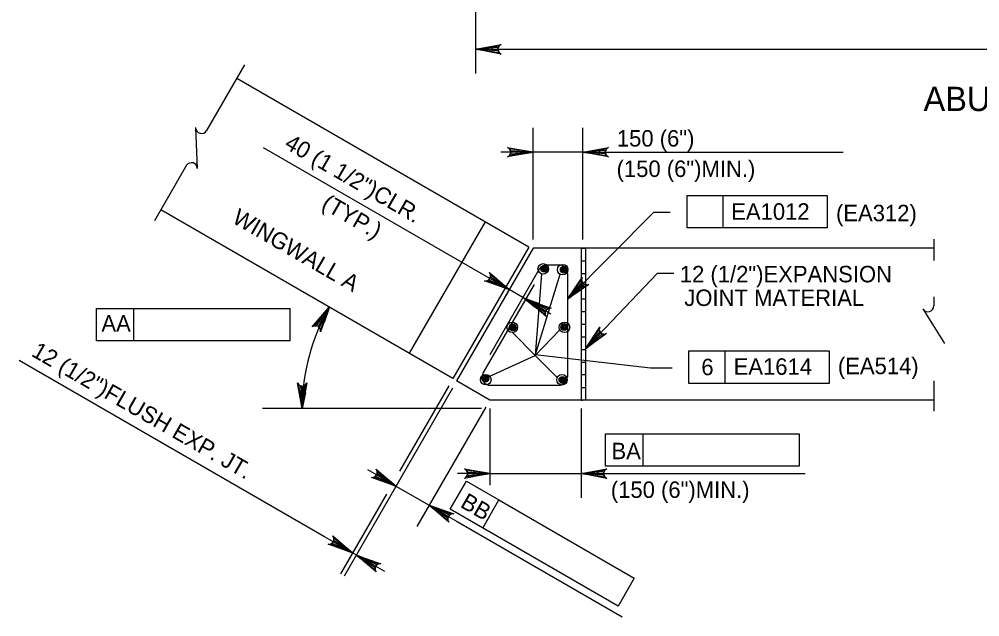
# Model space of a CAD drawing. Extents: x 634540 to 640306, y 296059 to 300275.
# Drawn here: x 638533.4 to 638708.4, y 297521.6 to 297630.5 of the extents above; entities that cross this region are included whole.
import ezdxf

# ---------------------------------------------------------------- set-up
doc = ezdxf.new("R2010")
doc.units = 0
for name, color, linetype in [('10', 7, 'Continuous'), ('3', 7, 'Continuous'), ('4', 7, 'Continuous'), ('5', 7, 'Continuous')]:
    doc.layers.add(name, color=color, linetype=linetype)

msp = doc.modelspace()

# ---------------------------------------------------------------- linework, layer by layer
at = {"layer": '10'}
for p, q in [((638626.27, 297588.96), (638573.04, 297619.69)), ((638612.43, 297564.99), (638559.2, 297595.72)), ((638618.28, 297593.57), (638604.43, 297569.6)), ((638626.27, 297588.96), (638612.43, 297564.99)), ((638627.05, 297588.78), (638613.09, 297564.6)), ((638700.05, 297588.78), (638627.05, 297588.78)), ((638635.82, 297588.77), (638635.82, 297561.09)), ((638636.59, 297588.77), (638636.59, 297561.09)), ((638619.17, 297561.09), (638613.09, 297564.6)), ((638700.05, 297561.09), (638619.17, 297561.09))]:
    msp.add_line(p, q, dxfattribs=at)
at = {"layer": '3'}
for p, q in [((638616.53, 297669.3), (638616.53, 297620.56)), ((638616.53, 297624.99), (638844.8, 297624.99)), ((638627.05, 297590.31), (638627.05, 297610.68)), ((638636.11, 297590.31), (638636.11, 297610.68)), ((638617.57, 297584.16), (638577.89, 297607.06)), ((638627.05, 297606.25), (638621.15, 297606.25)), ((638636.11, 297606.25), (638627.05, 297606.25)), ((638636.11, 297606.25), (638683.51, 297606.25)), ((638655.09, 297598.35), (638680.63, 297598.35)), ((638655.09, 297592.44), (638655.09, 297598.35)), ((638661.68, 297592.44), (638661.68, 297598.35)), ((638680.63, 297598.35), (638680.63, 297592.44)), ((638633.28, 297579.48), (638649.06, 297595.29)), ((638649.06, 297595.29), (638652.01, 297595.29)), ((638680.63, 297592.44), (638655.09, 297592.44)), ((638622.68, 297581.2), (638617.57, 297584.16)), ((638636.59, 297570.41), (638649.72, 297584.22)), ((638649.72, 297584.22), (638652.67, 297584.22)), ((638622.44, 297580.79), (638620.46, 297577.37)), ((638547.46, 297577.77), (638554.31, 297577.77)), ((638547.46, 297571.87), (638547.46, 297577.77)), ((638554.31, 297571.87), (638554.31, 297577.77)), ((638554.31, 297577.77), (638582.76, 297577.77)), ((638582.76, 297571.87), (638582.76, 297577.77)), ((638582.76, 297571.87), (638547.46, 297571.87)), ((638655.43, 297570.03), (638680.97, 297570.03)), ((638655.43, 297564.12), (638655.43, 297570.03)), ((638662.03, 297564.12), (638662.03, 297570.03)), ((638680.97, 297570.03), (638680.97, 297564.12)), ((638589.04, 297536.19), (638533.4, 297568.32)), ((638648.41, 297566.97), (638652.36, 297566.97)), ((638612.32, 297563.27), (638592.61, 297529.02)), ((638611.66, 297563.65), (638602.72, 297548.14)), ((638680.97, 297564.12), (638655.43, 297564.12)), ((638617.63, 297559.55), (638577.73, 297559.55)), ((638618.4, 297559.76), (638605.88, 297538.07)), ((638619.17, 297559.55), (638619.17, 297545.57)), ((638635.82, 297559.55), (638635.82, 297543.27)), ((638640.23, 297549.03), (638640.23, 297554.94)), ((638640.23, 297554.94), (638647.07, 297554.94)), ((638647.07, 297549.03), (638647.07, 297554.94)), ((638647.07, 297554.94), (638675.53, 297554.94)), ((638675.53, 297554.94), (638675.53, 297549.03)), ((638675.53, 297549.03), (638640.23, 297549.03)), ((638599.46, 297546.9), (638596.9, 297548.37)), ((638616.22, 297547.7), (638613.27, 297547.7)), ((638619.17, 297547.7), (638643.53, 297547.7)), ((638638.77, 297547.7), (638641.72, 297547.7)), ((638641.72, 297547.7), (638676.59, 297547.7)), ((638602.02, 297545.42), (638608.1, 297541.91)), ((638611.94, 297541.19), (638614.89, 297546.31)), ((638614.89, 297546.31), (638620.82, 297542.88)), ((638600.3, 297543.93), (638591.94, 297529.41)), ((638617.87, 297537.77), (638620.82, 297542.88)), ((638620.82, 297542.88), (638645.47, 297528.65)), ((638610.65, 297540.43), (638613.21, 297538.96)), ((638642.51, 297523.54), (638611.94, 297541.19)), ((638613.21, 297538.96), (638643.27, 297521.6)), ((638591.6, 297534.72), (638589.04, 297536.19)), ((638594.82, 297532.86), (638594.15, 297533.24)), ((638597.38, 297531.38), (638599.93, 297529.91)), ((638645.47, 297528.65), (638642.51, 297523.54))]:
    msp.add_line(p, q, dxfattribs=at)
for points in [[(638616.53, 297624.99), (638621.2, 297625.87), (638620.84, 297625.62), (638620.65, 297625.31), (638620.6, 297624.99), (638620.65, 297624.68), (638620.84, 297624.37), (638621.2, 297624.12), (638616.53, 297624.99), (638620.84, 297624.37), (638620.65, 297624.68), (638616.53, 297624.99), (638620.6, 297624.99), (638620.65, 297625.31), (638616.53, 297624.99), (638620.84, 297625.62)], [(638627.05, 297606.25), (638622.39, 297605.38), (638622.75, 297605.62), (638622.93, 297605.94), (638622.99, 297606.25), (638622.93, 297606.56), (638622.75, 297606.87), (638622.39, 297607.12), (638627.05, 297606.25), (638622.75, 297606.87), (638622.93, 297606.56), (638627.05, 297606.25), (638622.99, 297606.25), (638622.93, 297605.94), (638627.05, 297606.25), (638622.75, 297605.62)], [(638636.11, 297606.25), (638640.77, 297607.12), (638640.41, 297606.87), (638640.23, 297606.56), (638640.17, 297606.25), (638640.23, 297605.94), (638640.41, 297605.62), (638640.77, 297605.38), (638636.11, 297606.25), (638640.41, 297605.62), (638640.23, 297605.94), (638636.11, 297606.25), (638640.17, 297606.25), (638640.23, 297606.56), (638636.11, 297606.25), (638640.41, 297606.87)], [(638622.68, 297581.2), (638618.2, 297582.78), (638618.64, 297582.82), (638618.96, 297582.99), (638619.16, 297583.24), (638619.27, 297583.53), (638619.27, 297583.9), (638619.08, 297584.29), (638622.68, 297581.2), (638619.27, 297583.9), (638619.27, 297583.53), (638622.68, 297581.2), (638619.16, 297583.24), (638618.96, 297582.99), (638622.68, 297581.2), (638618.64, 297582.82)], [(638633.28, 297579.48), (638635.95, 297583.39), (638635.87, 297582.97), (638635.96, 297582.61), (638636.15, 297582.36), (638636.41, 297582.17), (638636.76, 297582.08), (638637.19, 297582.16), (638633.28, 297579.48), (638636.76, 297582.08), (638636.41, 297582.17), (638633.28, 297579.48), (638636.15, 297582.36), (638635.96, 297582.61), (638633.28, 297579.48), (638635.87, 297582.97)], [(638589.88, 297578), (638588.32, 297573.53), (638588.28, 297573.96), (638588.1, 297574.28), (638587.86, 297574.48), (638587.56, 297574.59), (638587.2, 297574.58), (638586.8, 297574.4), (638589.88, 297578), (638587.2, 297574.58), (638587.56, 297574.59), (638589.88, 297578), (638587.86, 297574.48), (638588.1, 297574.28), (638589.88, 297578), (638588.28, 297573.96)], [(638636.59, 297570.41), (638639.17, 297574.39), (638639.1, 297573.95), (638639.2, 297573.6), (638639.39, 297573.35), (638639.65, 297573.17), (638640, 297573.09), (638640.43, 297573.18), (638636.59, 297570.41), (638640, 297573.09), (638639.65, 297573.17), (638636.59, 297570.41), (638639.39, 297573.35), (638639.2, 297573.6), (638636.59, 297570.41), (638639.1, 297573.95)], [(638584.96, 297559.55), (638584.08, 297564.21), (638584.33, 297563.86), (638584.65, 297563.67), (638584.96, 297563.62), (638585.27, 297563.67), (638585.58, 297563.86), (638585.83, 297564.21), (638584.96, 297559.55), (638585.58, 297563.86), (638585.27, 297563.67), (638584.96, 297559.55), (638584.96, 297563.62), (638584.65, 297563.67), (638584.96, 297559.55), (638584.33, 297563.86)], [(638602.04, 297545.41), (638597.57, 297546.98), (638598, 297547.02), (638598.32, 297547.2), (638598.52, 297547.44), (638598.63, 297547.74), (638598.63, 297548.1), (638598.44, 297548.5), (638602.04, 297545.41), (638598.63, 297548.1), (638598.63, 297547.74), (638602.04, 297545.41), (638598.52, 297547.44), (638598.32, 297547.2), (638602.04, 297545.41), (638598, 297547.02)], [(638619.17, 297547.7), (638614.51, 297546.82), (638614.87, 297547.07), (638615.06, 297547.38), (638615.11, 297547.7), (638615.06, 297548.01), (638614.87, 297548.32), (638614.51, 297548.57), (638619.17, 297547.7), (638614.87, 297548.32), (638615.06, 297548.01), (638619.17, 297547.7), (638615.11, 297547.7), (638615.06, 297547.38), (638619.17, 297547.7), (638614.87, 297547.07)], [(638635.82, 297547.7), (638640.48, 297548.57), (638640.12, 297548.32), (638639.94, 297548.01), (638639.88, 297547.7), (638639.94, 297547.38), (638640.12, 297547.07), (638640.48, 297546.82), (638635.82, 297547.7), (638640.12, 297547.07), (638639.94, 297547.38), (638635.82, 297547.7), (638639.88, 297547.7), (638639.94, 297548.01), (638635.82, 297547.7), (638640.12, 297548.32)], [(638608.1, 297541.91), (638612.57, 297540.34), (638612.13, 297540.3), (638611.82, 297540.12), (638611.62, 297539.88), (638611.51, 297539.58), (638611.51, 297539.22), (638611.7, 297538.82), (638608.1, 297541.91), (638611.51, 297539.22), (638611.51, 297539.58), (638608.1, 297541.91), (638611.62, 297539.88), (638611.82, 297540.12), (638608.1, 297541.91), (638612.13, 297540.3)], [(638594.15, 297533.24), (638589.68, 297534.82), (638590.11, 297534.85), (638590.43, 297535.03), (638590.63, 297535.28), (638590.74, 297535.57), (638590.74, 297535.94), (638590.55, 297536.33), (638594.15, 297533.24), (638590.74, 297535.94), (638590.74, 297535.57), (638594.15, 297533.24), (638590.63, 297535.28), (638590.43, 297535.03), (638594.15, 297533.24), (638590.11, 297534.85)], [(638594.83, 297532.85), (638599.3, 297531.28), (638598.87, 297531.24), (638598.55, 297531.07), (638598.35, 297530.82), (638598.24, 297530.52), (638598.24, 297530.16), (638598.43, 297529.77), (638594.83, 297532.85), (638598.24, 297530.16), (638598.24, 297530.52), (638594.83, 297532.85), (638598.35, 297530.82), (638598.55, 297531.07), (638594.83, 297532.85), (638598.87, 297531.24)]]:
    msp.add_lwpolyline(points, dxfattribs=at)
for points in [[(638619.49, 297625.48), (638619.49, 297624.5), (638616.53, 297624.99)], [(638624.1, 297606.74), (638624.1, 297605.76), (638627.05, 297606.25)], [(638639.06, 297606.74), (638639.06, 297605.76), (638636.11, 297606.25)], [(638620.37, 297583.11), (638619.88, 297582.26), (638622.68, 297581.21)], [(638588.98, 297575.22), (638588.11, 297575.67), (638589.92, 297578.06)], [(638584.58, 297562.53), (638585.57, 297562.49), (638584.96, 297559.55)], [(638599.71, 297547.32), (638599.22, 297546.47), (638602.02, 297545.42)], [(638616.22, 297548.19), (638616.22, 297547.2), (638619.17, 297547.7)], [(638638.77, 297548.19), (638638.77, 297547.2), (638635.82, 297547.7)], [(638610.9, 297540.86), (638610.41, 297540.01), (638608.1, 297541.91)], [(638591.84, 297535.14), (638591.35, 297534.29), (638594.15, 297533.24)], [(638597.62, 297531.81), (638597.13, 297530.96), (638594.82, 297532.86)]]:
    msp.add_lwpolyline(points, close=True, dxfattribs=at)
msp.add_arc((638621.97, 297559.55), 37.01, 150.1038, 180, dxfattribs=at)
at = {"layer": '4'}
for p, q in [((638574.47, 297622.17), (638567.54, 297610.18)), ((638565.55, 297610.71), (638565.83, 297603.29)), ((638563.9, 297603.87), (638558.06, 297593.75)), ((638700.05, 297590.42), (638700.05, 297586.53)), ((638700.05, 297579.9), (638700.05, 297578.23)), ((638698.06, 297577.7), (638702.01, 297571.41)), ((638700.05, 297564.58), (638700.05, 297559.07))]:
    msp.add_line(p, q, dxfattribs=at)
for centre, start, end in [((638566.62, 297610.71), 180, 330), ((638564.77, 297603.25), 2.1328, 144.6714), ((638698.98, 297578.23), 210, 0)]:
    msp.add_arc(centre, 1.07, start, end, dxfattribs=at)
at = {"layer": '5'}
for p, q in [((638635.82, 297588.77), (638636.59, 297588.78)), ((638629.49, 297585.69), (638631.74, 297585.69)), ((638635.82, 297586.47), (638636.59, 297586.47)), ((638628.16, 297584.92), (638619.14, 297569.3)), ((638628.57, 297584.07), (638627.39, 297569.21)), ((638627.39, 297569.21), (638631.95, 297584)), ((638633.28, 297584.16), (638633.28, 297565.31)), ((638635.82, 297584.16), (638636.59, 297584.16)), ((638627.22, 297582.15), (638617.95, 297566.08)), ((638625.18, 297579.76), (638622.68, 297581.21)), ((638635.82, 297581.86), (638636.59, 297581.86)), ((638625.84, 297579.38), (638630.29, 297576.81)), ((638635.82, 297579.55), (638636.59, 297579.55)), ((638635.82, 297577.24), (638636.59, 297577.24)), ((638623.29, 297573.38), (638627.39, 297569.21)), ((638627.39, 297569.21), (638631.91, 297573.87)), ((638635.82, 297574.93), (638636.59, 297574.93)), ((638635.82, 297572.63), (638636.59, 297572.63)), ((638635.82, 297570.32), (638636.59, 297570.32)), ((638619.14, 297565.41), (638627.39, 297569.21)), ((638627.39, 297569.38), (638648.41, 297566.97)), ((638627.39, 297569.21), (638631.45, 297565.22)), ((638635.82, 297568.01), (638636.59, 297568.01)), ((638635.82, 297565.71), (638636.59, 297565.71)), ((638619.28, 297563.78), (638631.74, 297563.78)), ((638635.82, 297563.4), (638636.59, 297563.4)), ((638635.82, 297561.09), (638636.04, 297561.09))]:
    msp.add_line(p, q, dxfattribs=at)
msp.add_lwpolyline([(638627.98, 297578.71), (638627.49, 297577.86), (638625.18, 297579.76)], close=True, dxfattribs=at)
msp.add_lwpolyline([(638625.84, 297579.38), (638630.32, 297577.81), (638629.88, 297577.77), (638629.56, 297577.59), (638629.36, 297577.35), (638629.25, 297577.05), (638629.26, 297576.69), (638629.44, 297576.29), (638625.84, 297579.38), (638629.26, 297576.69), (638629.25, 297577.05), (638625.84, 297579.38), (638629.36, 297577.35), (638629.56, 297577.59), (638625.84, 297579.38), (638629.88, 297577.77)], dxfattribs=at)
for centre, radius in [((638628.88, 297584.98), 0.962), ((638629.09, 297585), 0.625), ((638632.43, 297584.84), 0.962), ((638629.09, 297585), 0.469), ((638629.09, 297585), 0.313), ((638629.09, 297585), 0.156), ((638632.63, 297584.85), 0.625), ((638632.63, 297584.85), 0.469), ((638632.63, 297584.85), 0.313), ((638632.63, 297584.85), 0.156), ((638623.23, 297574.34), 0.962), ((638632.75, 297574.34), 0.962), ((638623.32, 297574.32), 0.625), ((638623.32, 297574.32), 0.469), ((638623.32, 297574.32), 0.313), ((638623.32, 297574.32), 0.156), ((638632.7, 297574.39), 0.625), ((638632.7, 297574.39), 0.469), ((638632.7, 297574.39), 0.313), ((638632.7, 297574.39), 0.156), ((638618.41, 297564.79), 0.962), ((638618.34, 297565), 0.625), ((638618.34, 297565), 0.469), ((638618.34, 297565), 0.313), ((638618.34, 297565), 0.156), ((638632.3, 297564.78), 0.962), ((638632.39, 297564.76), 0.625), ((638632.39, 297564.76), 0.469), ((638632.39, 297564.76), 0.313), ((638632.39, 297564.76), 0.156)]:
    msp.add_circle(centre, radius, dxfattribs=at)
for centre, start, end in [((638629.49, 297584.15), 90, 150), ((638631.74, 297584.15), 0, 90), ((638619.28, 297565.31), 150, 270), ((638631.74, 297565.31), 270, 0)]:
    msp.add_arc(centre, 1.54, start, end, dxfattribs=at)

# ---------------------------------------------------------------- texts
at = {"layer": '3'}
for s, height, p in [('ABUTMENT PLAN', 4.4294, (638698.18, 297613.73)), ('150 (6")', 3, (638642.3, 297607.26)), ('(150 (6")MIN.)', 3.0001, (638642.25, 297601.72)), ('EA1012', 3, (638663.14, 297593.93)), ('(EA312)', 3, (638682.23, 297593.66)), ('12 (1/2")EXPANSION', 3.0001, (638653.77, 297582.53)), ('JOINT MATERIAL', 3.0001, (638654.59, 297578.22)), ('AA', 3, (638548.38, 297573.55)), ('6', 3, (638657.69, 297565.61)), ('EA1614', 3, (638663.58, 297565.69)), ('(EA514)', 3, (638682.57, 297565.8)), ('BA', 3, (638641.32, 297550.31)), ('(150 (6")MIN.)', 3.0001, (638641.2, 297543.26))]:
    msp.add_text(s, height=height, dxfattribs=at).set_placement(p)
for s, height, p in [(' 40 (1 1/2")CLR.', 3.0001, (638580.56, 297607.65)), ('(TYP.)', 3, (638588.29, 297596.13)), ('WINGWALL A', 3, (638572, 297593.51)), ('12 (1/2")FLUSH EXP. JT.', 3.0001, (638535.44, 297569.22)), ('BB', 3, (638613.59, 297541.7))]:
    msp.add_text(s, height=height, rotation=330, dxfattribs=at).set_placement(p)

doc.saveas('drawing.dxf')
